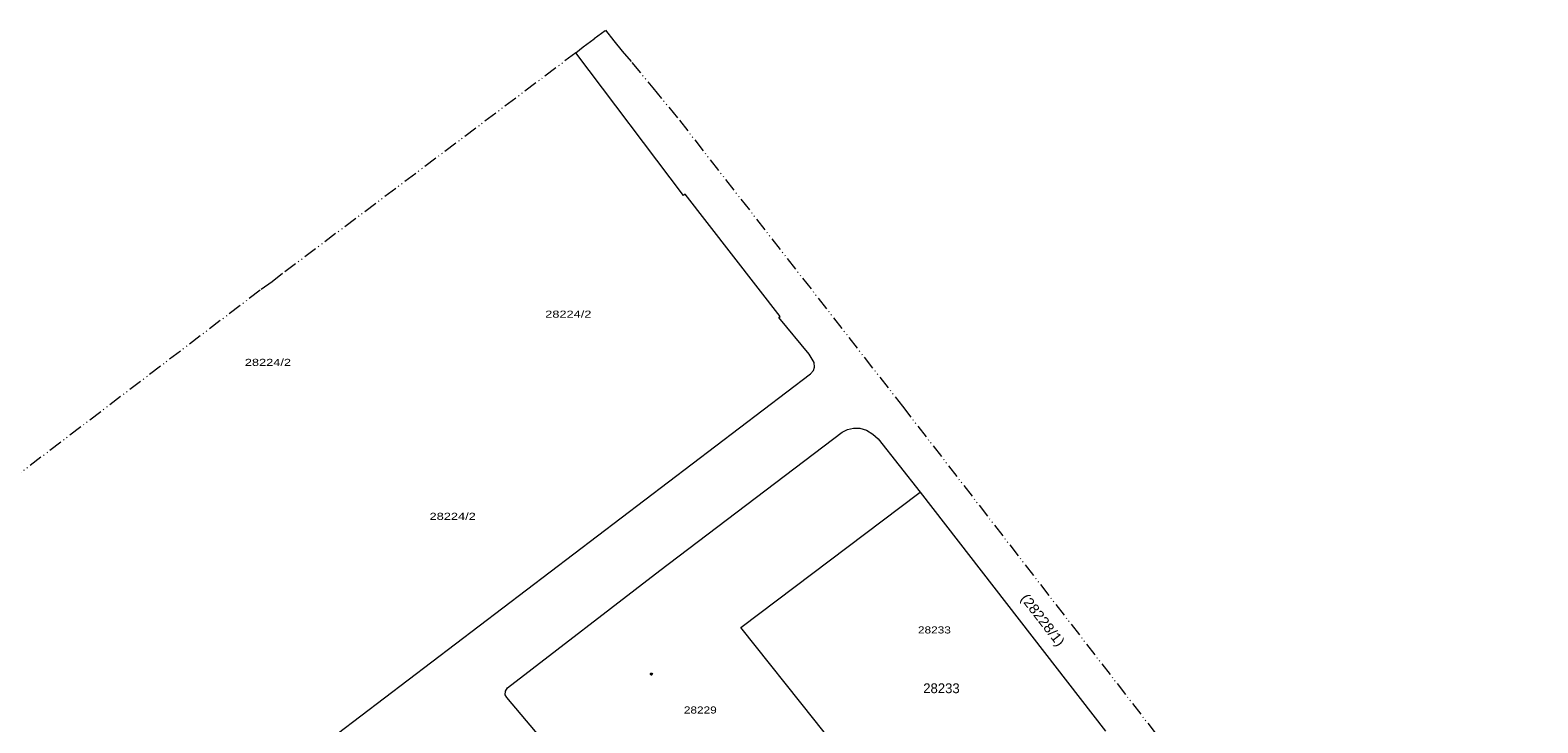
# Model space of a CAD drawing. Extents: x 650553 to 652508, y 239277 to 241647.
# Drawn here: x 651648 to 652201, y 241393 to 241647 of the extents above; entities that cross this region are included whole.
import ezdxf

# ---------------------------------------------------------------- set-up
doc = ezdxf.new("R2010")
doc.units = 0
doc.header["$PDMODE"] = 32
doc.header["$PDSIZE"] = 0.5
doc.linetypes.add('DASH_DOUBLE_DOT', pattern=[9.2, 5, -1.2, 0.3, -1.2, 0.3, -1.2])
for name, color, linetype in [('19', 7, 'Continuous'), ('20', 7, 'Continuous'), ('6', 7, 'Continuous')]:
    doc.layers.add(name, color=color, linetype=linetype)
for name, color, linetype, lineweight in [('2', 7, 'DASH_DOUBLE_DOT', 13), ('3', 7, 'Continuous', 13), ('5', 7, 'Continuous', 13), ('52', 7, 'DASH_DOUBLE_DOT', 13)]:
    doc.layers.add(name, color=color, linetype=linetype, lineweight=lineweight)

msp = doc.modelspace()

# ---------------------------------------------------------------- linework, layer by layer
at = {"layer": '2'}
msp.add_lwpolyline([(651848.117, 241638.653), (651740.452, 241557.584), (651736.648, 241554.597), (651732.165, 241551.441), (651617.113, 241463.771)], dxfattribs=at)
at = {"layer": '3'}
for points in [[(651370, 241074.13), (651372.52, 241075.56), (651374.02, 241076.72), (651375, 241077.5), (651380.8, 241082.08), (651418.74, 241114.72), (651492.17, 241180.79), (651501.81, 241189.21), (651522.184, 241207.047), (651510.315, 241222.672), (651514.337, 241226.015), (651528.272, 241211.629), (651534.34, 241216.71), (651934.25, 241520.81), (651935.39, 241521.93), (651935.77, 241523.21), (651935.63, 241524.91), (651933.75, 241527.93), (651922.73, 241541.47), (651923.22, 241541.86), (651888.26, 241586.69), (651887.65, 241586.26), (651848.117, 241638.653)], [(651890.22, 241320.18), (651838.628, 241383.147), (651822.772, 241401.85), (651822.162, 241402.878), (651822.324, 241404.195), (651822.971, 241405.485), (651878.911, 241448.551), (651945.895, 241499.372), (651947.853, 241500.347), (651950.067, 241500.78), (651952.377, 241500.815), (651954.829, 241500.052), (651957.24, 241498.606), (651959.178, 241496.936), (651974.53, 241477.34), (652042.61, 241389.52)]]:
    msp.add_lwpolyline(points, dxfattribs=at)
at = {"layer": '5'}
msp.add_line((651954.88, 241369.62), (651935.96, 241393.37), dxfattribs=at)
msp.add_lwpolyline([(651935.96, 241393.37), (651908.67, 241427.6), (651974.03, 241476.962), (651974.53, 241477.34)], dxfattribs=at)
at = {"layer": '52'}
msp.add_lwpolyline([(651848.117, 241638.653), (651850.85, 241640.826), (651854.855, 241643.843), (651859.061, 241646.967), (651862.077, 241642.993), (651865.187, 241639.299), (651868.69, 241635.11), (651876.454, 241625.813), (651886.134, 241613.883), (651968.083, 241508.86), (652062.325, 241387.051), (652163.19, 241255.731), (652270.107, 241116.584), (652399.768, 240948.012), (652508.14, 240805.294)], dxfattribs=at)
at = {"layer": '6'}
msp.add_point((651875.893, 241410.497), dxfattribs=at)

# ---------------------------------------------------------------- texts
at = {"layer": '19', "width": 1.1}
msp.add_text('(28228/1)', height=3.6, rotation=307.784, dxfattribs=at).set_placement((652011.237, 241438.235))
at = {"layer": '19'}
msp.add_text('28233', height=3.6, dxfattribs=at).set_placement((651975.697, 241403.497))
at = {"layer": '20'}
for s, width, p in [('28224/2', 1.35, (651836.876, 241541.378)), ('28224/2', 1.35, (651726.567, 241523.667)), ('28224/2', 1.35, (651794.414, 241467.132)), ('28233', 1.25, (651973.757, 241425.418)), ('28229', 1.25, (651887.79, 241396.012))]:
    msp.add_text(s, height=2.6, dxfattribs=dict(at, width=width)).set_placement(p)

doc.saveas('drawing.dxf')
